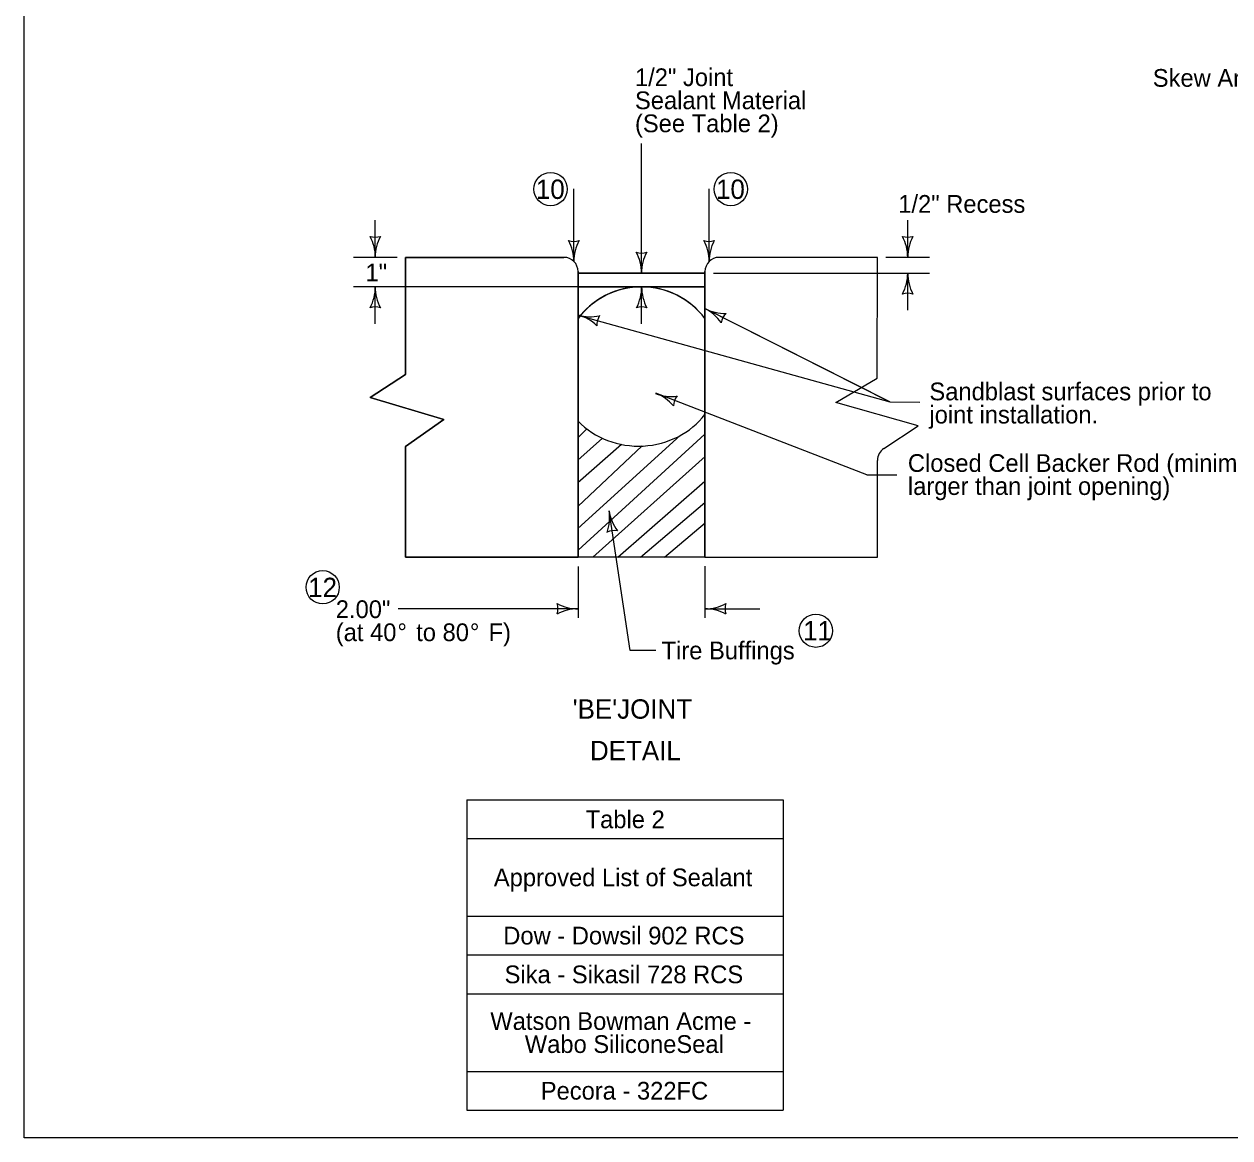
# Model space of a CAD drawing. Extents: x -2134934 to -2124557, y -2139046 to -2134021.
# Drawn here: x -2127734 to -2126647, y -2139046 to -2138041 of the extents above; entities that cross this region are included whole.
import ezdxf

# ---------------------------------------------------------------- set-up
doc = ezdxf.new("R2010")
doc.units = 0
for name, color, linetype in [('BridgeSuperStructureExisting', 7, 'Continuous'), ('Default', 7, 'Continuous'), ('dsnAlignmentStation', 7, 'Continuous'), ('dsnStdLabel', 7, 'Continuous')]:
    doc.layers.add(name, color=color, linetype=linetype)

msp = doc.modelspace()

# ---------------------------------------------------------------- linework, layer by layer
at = {"layer": 'BridgeSuperStructureExisting'}
for p, q in [((-2127335, -2138741), (-2127335, -2139020.9)), ((-2127335, -2138741), (-2127049.6, -2138741)), ((-2127049.6, -2138741), (-2127049.6, -2139020.9)), ((-2127335, -2138775.9), (-2127049.6, -2138775.9)), ((-2127335, -2138845.9), (-2127049.6, -2138845.9)), ((-2127335, -2138880.9), (-2127049.6, -2138880.9)), ((-2127335, -2138915.9), (-2127049.6, -2138915.9)), ((-2127335, -2138985.9), (-2127049.6, -2138985.9)), ((-2127335, -2139020.9), (-2127049.6, -2139020.9))]:
    msp.add_line(p, q, dxfattribs=at)
for points in [[(-2127247.5, -2138251.4), (-2127390.3, -2138251.4), (-2127390.3, -2138357), (-2127422.2, -2138377.8), (-2127355.7, -2138397.6), (-2127390.3, -2138422.2), (-2127390.3, -2138521.9), (-2127234.7, -2138521.9), (-2127234.7, -2138306.6)], [(-2126959, -2138423.9), (-2126928, -2138403.3), (-2127002.3, -2138382.4), (-2126964.8, -2138360.4), (-2126964.7, -2138251.4), (-2127107.5, -2138251.4)], [(-2127234.7, -2138306.6), (-2127234.7, -2138303.5), (-2127234.7, -2138278), (-2127234.7, -2138265.6), (-2127234.7, -2138264.2)], [(-2127120.3, -2138264.2), (-2127120.3, -2138265.6), (-2127120.3, -2138265.6), (-2127120.3, -2138271.9), (-2127120.3, -2138297.7), (-2127120.3, -2138300.4), (-2127120.3, -2138521.9), (-2126964.7, -2138521.9), (-2126964.7, -2138434.6)]]:
    msp.add_lwpolyline(points, dxfattribs=at)
for centre in [(-2127259.5, -2138189.8), (-2127097, -2138189.8), (-2127465.1, -2138549.1), (-2127020.2, -2138588.3)]:
    msp.add_circle(centre, 15, dxfattribs=at)
for centre, radius, start, end in [((-2127417.7, -2138217.7), 15.5, 252.2666, 287.7333), ((-2127457.8, -2138251.4), 40.2, 360, 28.0725), ((-2127377.5, -2138251.4), 40.2, 151.9275, 180), ((-2127238.5, -2138221.5), 15.5, 252.2666, 287.7333), ((-2127278.7, -2138255.2), 40.2, 360, 28.0725), ((-2127198.3, -2138255.2), 40.2, 151.9275, 180), ((-2127116.6, -2138221.5), 15.5, 252.2666, 287.7333), ((-2127156.7, -2138255.2), 40.2, 360, 28.0725), ((-2127076.4, -2138255.2), 40.2, 151.9275, 180), ((-2126937.4, -2138217.7), 15.5, 252.2666, 287.7333), ((-2126977.6, -2138251.4), 40.2, 360, 28.0725), ((-2126897.2, -2138251.4), 40.2, 151.9275, 180), ((-2127177.5, -2138232), 15.5, 252.2666, 287.7333), ((-2127217.7, -2138265.6), 40.2, 360, 28.0725), ((-2127137.3, -2138265.6), 40.2, 151.9275, 180), ((-2127247.5, -2138264.2), 12.8, 0, 90), ((-2127107.5, -2138264.2), 12.8, 90, 180), ((-2126977.6, -2138265.6), 40.2, 331.9275, 0), ((-2126897.2, -2138265.6), 40.2, 180, 208.0725), ((-2127457.8, -2138278), 40.2, 331.9275, 0), ((-2127377.5, -2138278), 40.2, 180, 208.0725), ((-2127217.5, -2138278), 40.2, 331.9275, 0), ((-2127137.2, -2138278), 40.2, 180, 208.0725), ((-2126937.4, -2138299.3), 15.5, 72.2667, 107.7334), ((-2127417.7, -2138311.6), 15.5, 72.2667, 107.7334), ((-2127245.5, -2138342.2), 40.2, 46.3768, 74.4493), ((-2127224, -2138264.8), 40.2, 254.4493, 282.5218), ((-2127202.3, -2138312.5), 15.5, 146.716, 182.1827), ((-2127177.4, -2138311.6), 15.5, 72.2667, 107.7334), ((-2127138.4, -2138333.5), 40.2, 35.1757, 63.2482), ((-2127102.2, -2138261.8), 40.2, 243.2482, 271.3206), ((-2127090.2, -2138312.8), 15.5, 135.5148, 170.9815), ((-2127177.5, -2138349.5), 71.5, 143.1385, 143.139), ((-2127179.1, -2138411.6), 40.2, 40.8833, 68.9558), ((-2127150.3, -2138336.7), 40.2, 248.9558, 277.0283), ((-2127133.3, -2138386.2), 15.5, 141.2225, 176.6892), ((-2126951.9, -2138434.6), 12.8, 123.5371, 179.992), ((-2126951.9, -2138434.6), 12.8, 179.992, 180), ((-2127246.5, -2138486.2), 40.2, 340.591, 8.6635), ((-2127167, -2138474.1), 40.2, 188.6635, 216.7359), ((-2127201.7, -2138513.4), 15.5, 80.9301, 116.3968), ((-2127268.4, -2138568.5), 15.5, 342.2666, 17.7333), ((-2127234.7, -2138528.3), 40.2, 241.9275, 270), ((-2127120.3, -2138528.3), 40.2, 270, 298.0725), ((-2127086.6, -2138568.5), 15.5, 162.2666, 197.7333), ((-2127234.7, -2138608.7), 40.2, 90, 118.0725), ((-2127120.3, -2138608.7), 40.2, 61.9275, 90)]:
    msp.add_arc(centre, radius, start, end, dxfattribs=at)
at = {"layer": 'Default'}
for p, q in [((-2127390.3, -2138357), (-2127390.3, -2138251.4)), ((-2127390.3, -2138251.4), (-2127247.5, -2138251.4)), ((-2127234.7, -2138264.2), (-2127234.7, -2138265.6)), ((-2127234.7, -2138294.2), (-2127234.7, -2138265.6)), ((-2127234.7, -2138265.6), (-2127234.7, -2138521.9)), ((-2127234.7, -2138265.6), (-2127120.3, -2138265.6)), ((-2127120.3, -2138521.9), (-2127120.3, -2138264.2)), ((-2127120.3, -2138265.6), (-2127120.3, -2138300.4)), ((-2127120.3, -2138265.6), (-2127120.3, -2138278)), ((-2127120.3, -2138278), (-2127234.7, -2138278)), ((-2127234.7, -2138278), (-2127234.7, -2138306.6)), ((-2127234.7, -2138306.6), (-2127234.7, -2138278)), ((-2127177.9, -2138278), (-2127177.1, -2138278)), ((-2127120.3, -2138306.5), (-2127120.3, -2138278)), ((-2127120.3, -2138278), (-2127120.3, -2138306.6)), ((-2127120.7, -2138297.4), (-2126953.4, -2138381.8)), ((-2127422.2, -2138377.8), (-2127390.3, -2138357)), ((-2127355.7, -2138397.6), (-2127422.2, -2138377.8)), ((-2127390.3, -2138422.2), (-2127355.7, -2138397.6)), ((-2127234.9, -2138414.2), (-2127226.7, -2138406.2)), ((-2127234.8, -2138496.1), (-2127142.7, -2138412.2)), ((-2127234.7, -2138515.6), (-2127120.5, -2138410.9)), ((-2127390.3, -2138521.9), (-2127390.3, -2138422.2)), ((-2127234.9, -2138434.3), (-2127212.7, -2138414.7)), ((-2127234.9, -2138476.1), (-2127176.9, -2138421.6)), ((-2127234.8, -2138454.7), (-2127195.6, -2138419.9)), ((-2127221.4, -2138521.9), (-2127120.1, -2138431)), ((-2126964.7, -2138521.9), (-2126964.7, -2138434.6)), ((-2127198.8, -2138522), (-2127120.3, -2138453.4)), ((-2127178.5, -2138522), (-2127120.3, -2138472.6)), ((-2127156.7, -2138521.9), (-2127120.2, -2138491.1)), ((-2127120.3, -2138521.9), (-2127390.3, -2138521.9)), ((-2127120.3, -2138521.9), (-2126964.7, -2138521.9))]:
    msp.add_line(p, q, dxfattribs=at)
for points in [[(-2126959, -2138423.9), (-2126928, -2138403.3), (-2127002.3, -2138382.4), (-2126964.8, -2138360.4), (-2126964.7, -2138251.4), (-2127107.5, -2138251.4)], [(-2127120.3, -2138297.6), (-2127120.3, -2138289.4), (-2127120.3, -2138289.3), (-2127120.3, -2138289.2), (-2127120.3, -2138278), (-2127120.3, -2138265.6), (-2127234.7, -2138265.6), (-2127234.7, -2138306.6)], [(-2127120.3, -2138264.2), (-2127120.3, -2138265.6), (-2127120.3, -2138300.4), (-2127120.3, -2138521.9), (-2127129.6, -2138521.9)], [(-2127234.7, -2138306.6), (-2127234.7, -2138278), (-2127177.7, -2138278)], [(-2127234.7, -2138306.6), (-2127234.7, -2138278), (-2127177.7, -2138278)], [(-2127234.7, -2138306.6), (-2127234.7, -2138278), (-2127177.7, -2138278)], [(-2127234.7, -2138306.6), (-2127234.7, -2138278), (-2127177.7, -2138278)], [(-2127234.7, -2138306.6), (-2127234.7, -2138278), (-2127177.7, -2138278)], [(-2127234.7, -2138306.6), (-2127234.7, -2138278), (-2127177.7, -2138278)], [(-2127234.7, -2138306.6), (-2127234.7, -2138278), (-2127177.7, -2138278)], [(-2127234.7, -2138306.6), (-2127234.7, -2138278), (-2127177.7, -2138278)], [(-2127234.7, -2138306.6), (-2127234.7, -2138278), (-2127177.7, -2138278)], [(-2127234.7, -2138306.6), (-2127234.7, -2138278), (-2127177.7, -2138278)], [(-2127234.7, -2138306.6), (-2127234.7, -2138278), (-2127177.7, -2138278)], [(-2127234.7, -2138306.6), (-2127234.7, -2138278), (-2127177.7, -2138278)], [(-2127234.7, -2138306.6), (-2127234.7, -2138278), (-2127177.7, -2138278)], [(-2127234.7, -2138306.6), (-2127234.7, -2138278), (-2127177.7, -2138278)], [(-2127234.7, -2138306.6), (-2127234.7, -2138278), (-2127177.7, -2138278)], [(-2127234.7, -2138306.6), (-2127234.7, -2138278), (-2127177.7, -2138278)], [(-2127234.7, -2138306.6), (-2127234.7, -2138278), (-2127177.7, -2138278)], [(-2127234.7, -2138306.6), (-2127234.7, -2138278), (-2127177.7, -2138278)], [(-2127234.7, -2138306.6), (-2127234.7, -2138278), (-2127177.7, -2138278)], [(-2127234.7, -2138306.6), (-2127234.7, -2138278), (-2127177.7, -2138278)], [(-2127234.7, -2138306.6), (-2127234.7, -2138278), (-2127177.7, -2138278)], [(-2127234.7, -2138306.6), (-2127234.7, -2138278), (-2127177.7, -2138278)], [(-2127234.7, -2138306.6), (-2127234.7, -2138278), (-2127177.7, -2138278)], [(-2127234.7, -2138306.6), (-2127234.7, -2138278), (-2127177.7, -2138278)], [(-2127234.7, -2138306.6), (-2127234.7, -2138278), (-2127177.7, -2138278)], [(-2127234.7, -2138306.6), (-2127234.7, -2138278), (-2127177.7, -2138278)], [(-2127234.7, -2138306.6), (-2127234.7, -2138278), (-2127177.7, -2138278)], [(-2127234.7, -2138306.6), (-2127234.7, -2138278), (-2127177.7, -2138278)], [(-2127234.7, -2138306.6), (-2127234.7, -2138278), (-2127177.7, -2138278)], [(-2127234.7, -2138306.6), (-2127234.7, -2138278), (-2127177.7, -2138278)], [(-2127234.7, -2138306.6), (-2127234.7, -2138278), (-2127177.7, -2138278)], [(-2127234.7, -2138306.6), (-2127234.7, -2138278), (-2127177.7, -2138278)], [(-2127234.7, -2138306.6), (-2127234.7, -2138278), (-2127177.7, -2138278)], [(-2127234.7, -2138306.6), (-2127234.7, -2138278), (-2127177.7, -2138278)], [(-2127177.4, -2138278), (-2127120.3, -2138278), (-2127120.3, -2138306.6)], [(-2127177.4, -2138278), (-2127120.3, -2138278), (-2127120.3, -2138306.6)], [(-2127177.4, -2138278), (-2127120.3, -2138278), (-2127120.3, -2138306.6)], [(-2127177.4, -2138278), (-2127120.3, -2138278), (-2127120.3, -2138306.6)], [(-2127177.4, -2138278), (-2127120.3, -2138278), (-2127120.3, -2138306.6)], [(-2127177.4, -2138278), (-2127120.3, -2138278), (-2127120.3, -2138306.6)], [(-2127177.4, -2138278), (-2127120.3, -2138278), (-2127120.3, -2138306.6)], [(-2127177.4, -2138278), (-2127120.3, -2138278), (-2127120.3, -2138306.6)], [(-2127177.4, -2138278), (-2127120.3, -2138278), (-2127120.3, -2138306.6)], [(-2127177.4, -2138278), (-2127120.3, -2138278), (-2127120.3, -2138306.6)], [(-2127177.4, -2138278), (-2127120.3, -2138278), (-2127120.3, -2138306.6)], [(-2127177.4, -2138278), (-2127120.3, -2138278), (-2127120.3, -2138306.6)], [(-2127177.4, -2138278), (-2127120.3, -2138278), (-2127120.3, -2138306.6)], [(-2127177.4, -2138278), (-2127120.3, -2138278), (-2127120.3, -2138306.6)], [(-2127177.4, -2138278), (-2127120.3, -2138278), (-2127120.3, -2138306.6)], [(-2127177.4, -2138278), (-2127120.3, -2138278), (-2127120.3, -2138306.6)], [(-2127177.4, -2138278), (-2127120.3, -2138278), (-2127120.3, -2138306.6)], [(-2127177.4, -2138278), (-2127120.3, -2138278), (-2127120.3, -2138306.6)], [(-2127177.4, -2138278), (-2127120.3, -2138278), (-2127120.3, -2138289.2), (-2127120.3, -2138289.3), (-2127120.3, -2138289.4), (-2127120.3, -2138306.6)], [(-2127120.3, -2138306.6), (-2127120.3, -2138306.5), (-2127120.3, -2138306.5), (-2127120.3, -2138297.7)]]:
    msp.add_lwpolyline(points, dxfattribs=at)
for centre, radius, start, end in [((-2127247.5, -2138264.2), 12.8, 0, 90), ((-2127107.5, -2138264.2), 12.8, 90, 180), ((-2127177.5, -2138349.5), 71.5, 36.8603, 143.1397), ((-2127177.5, -2138349.5), 71.5, 90.1278, 143.139), ((-2127177.5, -2138349.5), 71.5, 90.1278, 143.139), ((-2127177.5, -2138349.5), 71.5, 90.1278, 143.1385), ((-2127177.5, -2138349.5), 71.5, 90.1278, 143.1385), ((-2127177.5, -2138349.5), 71.5, 90.1278, 143.1385), ((-2127177.5, -2138349.5), 71.5, 90.1278, 143.1385), ((-2127177.5, -2138349.5), 71.5, 90.1278, 143.1385), ((-2127177.5, -2138349.5), 71.5, 90.1278, 143.1385), ((-2127177.5, -2138349.5), 71.5, 90.1278, 143.1385), ((-2127177.5, -2138349.5), 71.5, 90.1278, 143.1385), ((-2127177.5, -2138349.5), 71.5, 90.1278, 143.1385), ((-2127177.5, -2138349.5), 71.5, 90.1278, 143.1385), ((-2127177.5, -2138349.5), 71.5, 90.1278, 143.1385), ((-2127177.5, -2138349.5), 71.5, 90.1278, 143.1385), ((-2127177.5, -2138349.5), 71.5, 90.1278, 143.1385), ((-2127177.5, -2138349.5), 71.5, 90.1278, 143.1385), ((-2127177.5, -2138349.5), 71.5, 90.1278, 143.1385), ((-2127177.5, -2138349.5), 71.5, 90.1278, 143.1385), ((-2127177.5, -2138349.5), 71.5, 90.1278, 143.1385), ((-2127177.5, -2138349.5), 71.5, 90.1278, 143.1385), ((-2127177.5, -2138349.5), 71.5, 90.1278, 143.1385), ((-2127177.5, -2138349.5), 71.5, 90.1278, 143.1385), ((-2127177.5, -2138349.5), 71.5, 90.1278, 143.1385), ((-2127177.5, -2138349.5), 71.5, 90.1278, 143.1385), ((-2127177.5, -2138349.5), 71.5, 90.1278, 143.1385), ((-2127177.5, -2138349.5), 71.5, 90.1278, 143.1385), ((-2127177.5, -2138349.5), 71.5, 90.1278, 143.1385), ((-2127177.5, -2138349.5), 71.5, 90.1278, 143.1385), ((-2127177.5, -2138349.5), 71.5, 90.1278, 143.1385), ((-2127177.5, -2138349.5), 71.5, 90.1278, 143.1385), ((-2127177.5, -2138349.5), 71.5, 90.1278, 143.1385), ((-2127177.5, -2138349.5), 71.5, 90.1278, 143.1385), ((-2127177.5, -2138349.5), 71.5, 90.1278, 143.1385), ((-2127177.5, -2138349.5), 71.5, 98.1344, 143.1385), ((-2127177.5, -2138349.5), 71.5, 90.3158, 140.4626), ((-2127177.5, -2138349.5), 71.5, 90.1278, 98.1344), ((-2127177.5, -2138349.5), 71.5, 36.8603, 89.8704), ((-2127177.5, -2138349.5), 71.5, 36.8603, 89.8704), ((-2127177.5, -2138349.5), 71.5, 36.8603, 89.8704), ((-2127177.5, -2138349.5), 71.5, 36.8603, 89.8704), ((-2127177.5, -2138349.5), 71.5, 36.8603, 89.8704), ((-2127177.5, -2138349.5), 71.5, 36.8603, 89.8704), ((-2127177.5, -2138349.5), 71.5, 36.8603, 89.8704), ((-2127177.5, -2138349.5), 71.5, 36.8603, 89.8704), ((-2127177.5, -2138349.5), 71.5, 36.8603, 89.8704), ((-2127177.5, -2138349.5), 71.5, 36.8603, 89.8704), ((-2127177.5, -2138349.5), 71.5, 36.8603, 89.8704), ((-2127177.5, -2138349.5), 71.5, 36.8603, 89.8704), ((-2127177.5, -2138349.5), 71.5, 36.8603, 89.8704), ((-2127177.5, -2138349.5), 71.5, 36.8603, 89.8704), ((-2127177.5, -2138349.5), 71.5, 36.8603, 89.8704), ((-2127177.5, -2138349.5), 71.5, 36.8603, 89.8704), ((-2127177.5, -2138349.5), 71.5, 36.8603, 89.8704), ((-2127177.5, -2138349.5), 71.5, 36.8603, 89.8704), ((-2127177.5, -2138349.5), 71.5, 36.8603, 89.8704), ((-2127177.5, -2138349.5), 71.5, 36.8603, 89.6842), ((-2127177.5, -2138349.5), 71.5, 140.4626, 143.1385), ((-2127138.8, -2138333.3), 40.2, 62.5774, 63.2482), ((-2127102.6, -2138261.6), 40.2, 243.2482, 243.9147), ((-2126951.9, -2138434.6), 12.8, 123.5371, 180), ((-2126951.9, -2138434.6), 12.8, 123.5371, 180)]:
    msp.add_arc(centre, radius, start, end, dxfattribs=at)
for centre, start_param, end_param in [((-2127180.1, -2138344.6), 0.606648, 0.606655), ((-2127180.1, -2138355), 3.864857, 5.676062)]:
    msp.add_ellipse(centre, major_axis=(72.8, 0), ratio=0.91682, start_param=start_param, end_param=end_param, dxfattribs=at)
at = {"layer": 'dsnAlignmentStation'}
msp.add_lwpolyline([(-2127734.4, -2137035.9), (-2124599.4, -2137035.9), (-2124599.4, -2139045.9), (-2127734.4, -2139045.9)], close=True, dxfattribs=at)
at = {"layer": 'dsnStdLabel'}
for p, q in [((-2127177.5, -2138265.6), (-2127177.5, -2138148.7)), ((-2127238.5, -2138255.2), (-2127238.5, -2138189.6)), ((-2127116.6, -2138255.2), (-2127116.6, -2138189.6)), ((-2127417.7, -2138251.4), (-2127417.7, -2138217.9)), ((-2126937.4, -2138251.4), (-2126937.4, -2138217.9)), ((-2127397.9, -2138251.4), (-2127437.4, -2138251.4)), ((-2126917.7, -2138251.4), (-2126957.1, -2138251.4)), ((-2127112.7, -2138265.6), (-2126917.7, -2138265.6)), ((-2126937.4, -2138299.2), (-2126937.4, -2138265.6)), ((-2127202.3, -2138278), (-2127437.4, -2138278)), ((-2127417.7, -2138311.5), (-2127417.7, -2138278)), ((-2127177.4, -2138311.5), (-2127177.4, -2138278)), ((-2127234.8, -2138303.5), (-2126953.4, -2138381.8)), ((-2126953.4, -2138381.8), (-2127120.3, -2138297.7)), ((-2126974.1, -2138447.5), (-2127164.7, -2138374.1)), ((-2126953.4, -2138381.8), (-2126926.4, -2138382)), ((-2126974.1, -2138447.5), (-2126947.1, -2138447.7)), ((-2127187.6, -2138606.1), (-2127206.7, -2138480.1)), ((-2127234.7, -2138530.4), (-2127234.7, -2138576.8)), ((-2127120.3, -2138530.2), (-2127120.3, -2138576.8)), ((-2127234.7, -2138568.5), (-2127397, -2138568.5)), ((-2127120.3, -2138568.5), (-2127070.7, -2138568.5)), ((-2127164.6, -2138606.1), (-2127187.6, -2138606.1))]:
    msp.add_line(p, q, dxfattribs=at)

# ---------------------------------------------------------------- texts
at = {"layer": 'BridgeSuperStructureExisting'}
for s, p in [("   'BE'JOINT ", (-2127259.1, -2138667.7)), ('   DETAIL', (-2127243.5, -2138705.2))]:
    msp.add_text(s, height=17.5, dxfattribs=at).set_placement(p)
at = {"layer": 'dsnStdLabel'}
for s, height, p in [('1/2" Joint', 16, (-2127183.4, -2138096.9)), ('Skew Angle', 16, (-2126716.3, -2138097.5)), ('Sealant Material', 16, (-2127183.4, -2138117.7)), ('(See Table 2)', 16, (-2127183.4, -2138138.5)), ('10', 17.5, (-2127272.8, -2138198.7)), ('10', 17.5, (-2127110.3, -2138198.7)), ('1/2" Recess', 16, (-2126945.9, -2138211.2)), ('1"', 16, (-2127426.5, -2138273.1)), ('Sandblast surfaces prior to ', 16, (-2126917.8, -2138380.4)), ('joint installation.', 16, (-2126917.8, -2138401.3)), ('Closed Cell Backer Rod (minimum 25%', 16, (-2126937.2, -2138445)), ('larger than joint opening)', 16, (-2126937.2, -2138465.8)), ('12', 17.5, (-2127478.2, -2138558)), ('2.00"', 16, (-2127453.3, -2138576.9)), ('(at 40', 16, (-2127453.3, -2138597.7)), ('°', 16, (-2127397.7, -2138597.7)), (' to 80', 16, (-2127386.7, -2138597.7)), ('°', 16, (-2127332.3, -2138597.7)), (' F)', 16, (-2127321.4, -2138597.7)), ('11', 17.5, (-2127031.8, -2138597.1)), ('Tire Buffings', 16, (-2127159.4, -2138614.1)), ('Table 2', 16, (-2127227.9, -2138766.5)), ('Approved List of Sealant', 16, (-2127310.7, -2138818.9)), ('Dow - Dowsil 902 RCS', 16, (-2127302.2, -2138871.4)), ('Sika - Sikasil 728 RCS', 16, (-2127301, -2138906.4)), ('Watson Bowman Acme - ', 16, (-2127313.9, -2138948.5)), ('Wabo SiliconeSeal', 16, (-2127282.8, -2138969.3)), ('Pecora - 322FC', 16, (-2127268.4, -2139011.4))]:
    msp.add_text(s, height=height, dxfattribs=at).set_placement(p)

doc.saveas('drawing.dxf')
